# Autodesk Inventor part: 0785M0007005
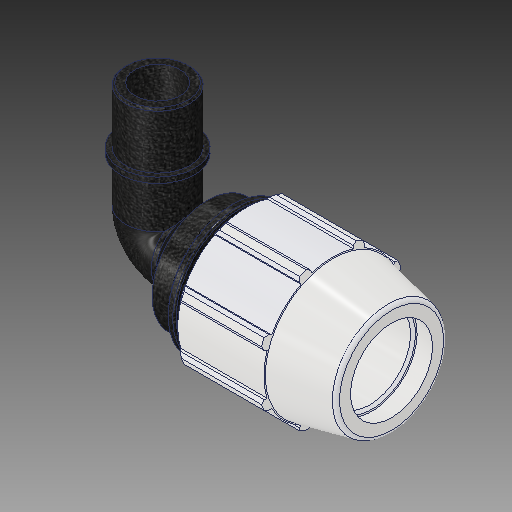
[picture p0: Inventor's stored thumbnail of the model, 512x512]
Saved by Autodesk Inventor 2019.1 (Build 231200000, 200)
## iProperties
Created: 2017-02
Part Number: 0785M0007005
Material: PVC-Piping
Description: PLASSON 90° ELBOW MALE ADAPTOR 3/4''-1/2''M
Document SubType Name: Modeling
Designer: KIM
Mass: 92.6774 g
Surface Area: 199.44 cm^2
Volume: 66.1981 cm^3
Density: 1.4 g/cm^3
Appearance: PTFE
Author: KIM
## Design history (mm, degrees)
derived "0785M0.ipt"
feature "Solid1::0785M0.ipt"
tag "TaggingFeature1"
body "Solid1"
other parameters: "d2" = 26.6, "d4" = 6.32883, "d5" = 18.9865, "d7" = 48.006, "d9" = 10.84943, "d11" = 2.53153, "d13" = 120 deg, "d14" = 35.91, "d15" = 12 deg, "d16" = 41.76522, "d18" = 1.33, "d19" = 35 deg, "d20" = 17.5 deg, "d21" = 44.64558, "d23" = 0, "d25" = 360 deg, "d27" = 0.96012, "d33" = 0.532, "d42" = 28.10002, "d43" = 1.44018, "d46" = 0.798, "d51" = 75.946, "d68" = 2.53153, "d72" = 42.926, "d73" = 20.955, "d74" = 18.034, "d75" = 24.09825, "d76" = 14.6685, "d77" = 19.8374, "d79" = 8.382, "d80" = 0.62865, "d83" = 0, "d84" = 0, "d91" = 36.0045, "d93" = 56.896, "d94" = 20.955, "d95" = 14.6685, "d96" = 7.5946, "d97" = 50 deg, "d_" = 26.6, "E_" = 48.006, "A_" = 75.946, "l_" = 56.896, "l_2" = 18.034, "A_1" = 42.926, "G_" = 20.955
